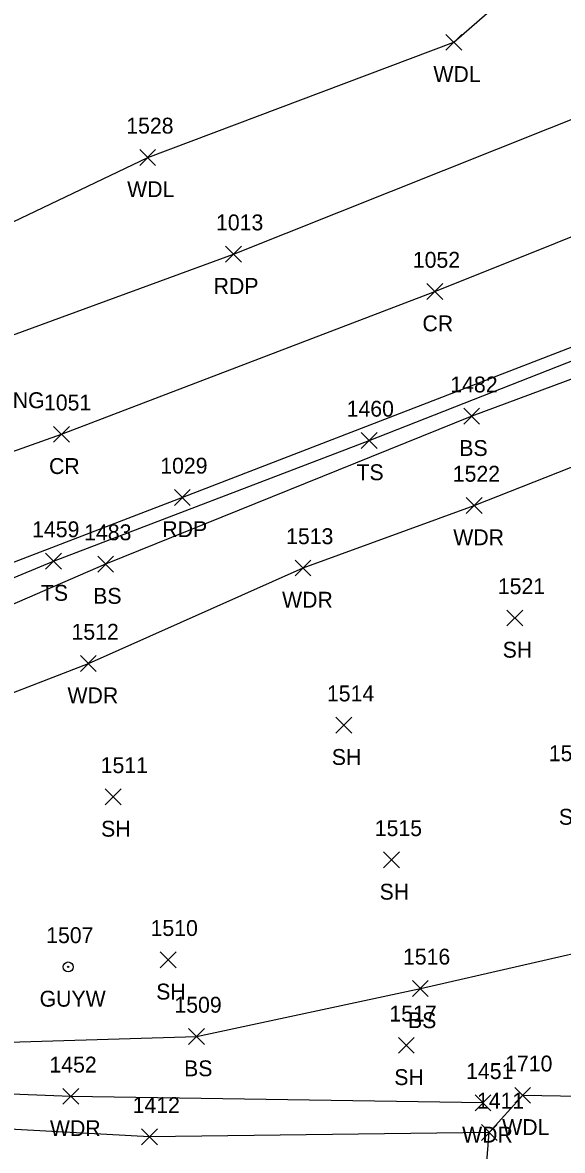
# Model space of a CAD drawing. Extents: x 1633660 to 1636532, y 388643 to 392631.
# Drawn here: x 1634156 to 1634224, y 388733.9 to 388875.9 of the extents above; entities that cross this region are included whole.
import ezdxf

# ---------------------------------------------------------------- set-up
doc = ezdxf.new("R2010")
doc.units = 0
for name, color, linetype in [('L_A', 7, 'Continuous'), ('L_I', 7, 'Continuous'), ('L_TIC', 7, 'Continuous'), ('LAWA', 7, 'Continuous'), ('LELB', 7, 'Continuous'), ('LSOGP', 7, 'Continuous'), ('P_A', 7, 'Continuous'), ('P_I', 7, 'Continuous'), ('P_TIC', 7, 'Continuous'), ('PET', 7, 'Continuous'), ('PEU', 7, 'Continuous'), ('PRC', 7, 'Continuous'), ('S_C', 7, 'Continuous'), ('U_A', 7, 'Continuous'), ('U_I', 7, 'Continuous'), ('UPGW', 7, 'Continuous')]:
    doc.layers.add(name, color=color, linetype=linetype)

msp = doc.modelspace()

# ---------------------------------------------------------------- linework, layer by layer
at = {"layer": 'L_TIC'}
for points in [[(1634209.32, 388872.4), (1634211.32, 388874.4)], [(1634211.32, 388872.4), (1634209.32, 388874.4)], [(1634170.78, 388857.91), (1634172.78, 388859.91)], [(1634172.78, 388857.91), (1634170.78, 388859.91)], [(1634211.56, 388825.33), (1634213.56, 388827.33)], [(1634213.56, 388825.33), (1634211.56, 388827.33)], [(1634198.65, 388822.28), (1634200.65, 388824.28)], [(1634200.65, 388822.28), (1634198.65, 388824.28)], [(1634211.88, 388814.09), (1634213.88, 388816.09)], [(1634213.88, 388814.09), (1634211.88, 388816.09)], [(1634158.93, 388807.1), (1634160.93, 388809.1)], [(1634160.93, 388807.1), (1634158.93, 388809.1)], [(1634165.48, 388806.72), (1634167.48, 388808.72)], [(1634167.48, 388806.72), (1634165.48, 388808.72)], [(1634190.33, 388806.23), (1634192.33, 388808.23)], [(1634192.33, 388806.23), (1634190.33, 388808.23)], [(1634216.98, 388799.94), (1634218.98, 388801.94)], [(1634218.98, 388799.94), (1634216.98, 388801.94)], [(1634163.31, 388794.2), (1634165.31, 388796.2)], [(1634165.31, 388794.2), (1634163.31, 388796.2)], [(1634195.47, 388786.44), (1634197.47, 388788.44)], [(1634197.47, 388786.44), (1634195.47, 388788.44)], [(1634166.42, 388777.41), (1634168.42, 388779.41)], [(1634168.42, 388777.41), (1634166.42, 388779.41)], [(1634201.48, 388769.48), (1634203.48, 388771.48)], [(1634203.48, 388769.48), (1634201.48, 388771.48)], [(1634173.36, 388756.91), (1634175.36, 388758.91)], [(1634175.36, 388756.91), (1634173.36, 388758.91)], [(1634205.1, 388753.31), (1634207.1, 388755.31)], [(1634207.1, 388753.31), (1634205.1, 388755.31)], [(1634176.92, 388747.25), (1634178.92, 388749.25)], [(1634178.92, 388747.25), (1634176.92, 388749.25)], [(1634203.33, 388746.14), (1634205.33, 388748.14)], [(1634205.33, 388746.14), (1634203.33, 388748.14)], [(1634161.11, 388739.72), (1634163.11, 388741.72)], [(1634163.11, 388739.72), (1634161.11, 388741.72)], [(1634212.99, 388738.9), (1634214.99, 388740.9)], [(1634214.99, 388738.9), (1634212.99, 388740.9)], [(1634217.98, 388739.85), (1634219.98, 388741.85)], [(1634219.98, 388739.85), (1634217.98, 388741.85)]]:
    msp.add_lwpolyline(points, dxfattribs=at)
at = {"layer": 'LAWA'}
for points in [[(1634029.51, 388906.75), (1634042.75, 388866.2), (1634043.29, 388851.86), (1634059.73, 388819.64), (1634086.07, 388831.91), (1634132.5, 388845.49), (1634141.64, 388844.49), (1634171.78, 388858.91), (1634210.32, 388873.4), (1634220.65, 388882.43), (1634241.67, 388885.4), (1634275.37, 388895.77), (1634312.68, 388911.32), (1634346.59, 388927.34), (1634362.7, 388937.8), (1634391.49, 388949.24), (1634419.55, 388956.24), (1634431.93, 388958.02)], [(1634130.81, 388762.97), (1634125.77, 388773.71), (1634128.73, 388780.91), (1634147.8, 388788.83), (1634164.31, 388795.2), (1634191.33, 388807.23), (1634212.88, 388815.09), (1634244.47, 388827.57), (1634270.05, 388838.56), (1634299.49, 388850.56), (1634310.77, 388855.38), (1634327.21, 388862.06), (1634379.71, 388881.61), (1634402.37, 388888.88), (1634424.47, 388897.46), (1634452.16, 388917.36), (1634475.03, 388932.29), (1634483.74, 388944.66)], [(1634213.99, 388739.9), (1634162.11, 388740.72), (1634125.6, 388742.11)], [(1634218.98, 388740.85), (1634254.67, 388740.24), (1634315.25, 388739.85)]]:
    msp.add_lwpolyline(points, dxfattribs=at)
at = {"layer": 'LELB'}
for points in [[(1634125.58, 388742.69), (1634122.38, 388746.52), (1634122.38, 388759.17), (1634119.85, 388773.41), (1634127.61, 388794.7), (1634159.93, 388808.1), (1634199.65, 388823.28), (1634240.01, 388839.13), (1634282.64, 388856.78), (1634322.87, 388872.9), (1634357.4, 388883.6), (1634392.97, 388895.75), (1634413.99, 388898.72), (1634440.42, 388919.1), (1634461.6, 388936.25), (1634480.46, 388947.83), (1634480.68, 388954.28)], [(1634339.35, 388869.85), (1634331.59, 388873.07), (1634294.07, 388857.44), (1634255.17, 388842.14), (1634212.56, 388826.33), (1634166.48, 388807.72), (1634131.43, 388792.51), (1634129.2, 388785.04)], [(1634139.55, 388754.21), (1634148.69, 388747.39), (1634177.92, 388748.25), (1634206.1, 388754.31), (1634231.04, 388759.99), (1634261.07, 388775.55)]]:
    msp.add_lwpolyline(points, dxfattribs=at)
at = {"layer": 'LSOGP'}
msp.add_lwpolyline([(1633892.15, 388670.64), (1633924.06, 388658.35), (1633934.83, 388655.28), (1633940.09, 388658.82), (1633943.21, 388657.8), (1633944.44, 388650.87), (1634007.22, 388659.11), (1634047.38, 388665.25), (1634068.61, 388685.27), (1634091.13, 388687.87), (1634119.65, 388686.04), (1634149.89, 388685.18), (1634208.91, 388690.49), (1634214.85, 388708.43), (1634213.54, 388715.93), (1634213.47, 388720.91), (1634213.51, 388722.74), (1634213.85, 388724.5), (1634214.78, 388736.17), (1634218.98, 388740.85), (1634254.67, 388740.24)], dxfattribs=at)
at = {"layer": 'P_TIC'}
for points in [[(1634181.59, 388845.73), (1634183.59, 388847.73)], [(1634183.59, 388845.73), (1634181.59, 388847.73)], [(1634206.93, 388841.02), (1634208.93, 388843.02)], [(1634208.93, 388841.02), (1634206.93, 388843.02)], [(1634159.92, 388823.06), (1634161.92, 388825.06)], [(1634161.92, 388823.06), (1634159.92, 388825.06)], [(1634175.14, 388815.11), (1634177.14, 388817.11)], [(1634177.14, 388815.11), (1634175.14, 388817.11)], [(1634171.01, 388734.63), (1634173.01, 388736.63)], [(1634173.01, 388734.63), (1634171.01, 388736.63)], [(1634213.78, 388735.17), (1634215.78, 388737.17)], [(1634215.78, 388735.17), (1634213.78, 388737.17)]]:
    msp.add_lwpolyline(points, dxfattribs=at)
at = {"layer": 'PET'}
for points in [[(1633681.12, 388754.49), (1633725.19, 388768.3), (1633776.36, 388776.79), (1633828.74, 388780.84), (1633883.05, 388781.87), (1633940.05, 388783.92), (1633980.78, 388788.35), (1634030.66, 388797.38), (1634082.16, 388811.29), (1634131.93, 388828.18), (1634182.59, 388846.73), (1634235.61, 388867.86)], [(1634233.66, 388838.29), (1634176.14, 388816.11), (1634127.42, 388797.4), (1634083.73, 388783.04), (1634035.91, 388770.06), (1633987.08, 388760.24), (1633936.49, 388754.34), (1633886.38, 388755.37), (1633827.16, 388754.09), (1633779.6, 388750.43), (1633734.35, 388742.35), (1633709.35, 388735.6), (1633689.74, 388728.83)]]:
    msp.add_lwpolyline(points, dxfattribs=at)
at = {"layer": 'PEU'}
msp.add_lwpolyline([(1634214.78, 388736.17), (1634172.01, 388735.63), (1634126.71, 388738.09), (1634117.16, 388746.33), (1634113.78, 388770.77), (1634118.36, 388791.5)], dxfattribs=at)
at = {"layer": 'PRC'}
msp.add_lwpolyline([(1633685.21, 388740.89), (1633722.47, 388753.09), (1633765.95, 388761.74), (1633808.84, 388766.45), (1633860.63, 388768.05), (1633911.93, 388769.08), (1633965.45, 388772.58), (1634019.68, 388781.06), (1634071.37, 388793.87), (1634111.14, 388806.36), (1634160.92, 388824.06), (1634207.93, 388842.02), (1634253.71, 388860.36), (1634302.74, 388880.25), (1634347.86, 388899.14), (1634390.05, 388916.89), (1634425.6, 388933.8), (1634443.27, 388943.77), (1634464.46, 388957.57)], dxfattribs=at)
at = {"layer": 'UPGW'}
for radius in [0.625, 0.0833]:
    msp.add_circle((1634161.77, 388757.01), radius, dxfattribs=at)

# ---------------------------------------------------------------- texts
at = {"layer": 'L_A'}
for s, p in [('WDL', (1634207.74, 388868.4)), ('WDL', (1634169.19, 388853.91)), ('BS', (1634211, 388821.33)), ('TS', (1634198.06, 388818.28)), ('WDR', (1634210.24, 388810.09)), ('TS', (1634158.34, 388803.1)), ('BS', (1634164.92, 388802.72)), ('WDR', (1634188.69, 388802.23)), ('SH', (1634216.46, 388795.94)), ('WDR', (1634161.68, 388790.2)), ('SH', (1634194.95, 388782.44)), ('SH', (1634223.53, 388774.91)), ('SH', (1634165.91, 388773.41)), ('SH', (1634200.97, 388765.48)), ('SH', (1634172.85, 388752.91)), ('BS', (1634204.54, 388749.31)), ('BS', (1634176.36, 388743.25)), ('SH', (1634202.82, 388742.14)), ('WDL', (1634216.4, 388735.85)), ('WDR', (1634159.47, 388735.72)), ('WDR', (1634211.35, 388734.9))]:
    msp.add_text(s, height=2, dxfattribs=at).set_placement(p)
at = {"layer": 'L_I'}
for s, p in [('1528', (1634169.08, 388861.91)), ('1482', (1634209.87, 388829.33)), ('1460', (1634196.82, 388826.28)), ('1522', (1634210.18, 388818.09)), ('1459', (1634157.23, 388811.1)), ('1483', (1634163.78, 388810.72)), ('1513', (1634189.2, 388810.23)), ('1521', (1634215.85, 388803.94)), ('1512', (1634162.19, 388798.2)), ('1514', (1634194.34, 388790.44)), ('1520', (1634222.27, 388782.91)), ('1511', (1634165.86, 388781.41)), ('1515', (1634200.36, 388773.48)), ('1510', (1634172.14, 388760.91)), ('1516', (1634203.91, 388757.31)), ('1509', (1634175.14, 388751.25)), ('1517', (1634202.2, 388750.14)), ('1452', (1634159.41, 388743.72)), ('1451', (1634211.86, 388742.9)), ('1710', (1634216.77, 388743.85))]:
    msp.add_text(s, height=2, dxfattribs=at).set_placement(p)
at = {"layer": 'P_A'}
for s, p in [('RDP', (1634180.08, 388841.73)), ('CR', (1634206.36, 388837.02)), ('CR', (1634159.36, 388819.06)), ('RDP', (1634173.62, 388811.11))]:
    msp.add_text(s, height=2, dxfattribs=at).set_placement(p)
at = {"layer": 'P_I'}
for s, p in [('1013', (1634180.38, 388849.73)), ('1052', (1634205.15, 388845.02)), ('1051', (1634158.72, 388827.06)), ('1029', (1634173.36, 388819.11)), ('1412', (1634169.88, 388738.63)), ('1411', (1634213.22, 388739.17))]:
    msp.add_text(s, height=2, dxfattribs=at).set_placement(p)
at = {"layer": 'S_C'}
msp.add_text('WINDING RD WARNING', height=2, dxfattribs=at).set_placement((1634128.64, 388827.35))
at = {"layer": 'U_A'}
msp.add_text('GUYW', height=2, dxfattribs=at).set_placement((1634158.17, 388752.01))
at = {"layer": 'U_I'}
msp.add_text('1507', height=2, dxfattribs=at).set_placement((1634159, 388760.01))

doc.saveas('drawing.dxf')
